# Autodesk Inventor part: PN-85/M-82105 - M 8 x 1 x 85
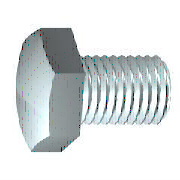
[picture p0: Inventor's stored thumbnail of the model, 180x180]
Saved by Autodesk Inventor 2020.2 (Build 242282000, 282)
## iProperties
Manager: www.cadconsulting.pl
Company: Fabian Stasiak CAD Consulting
Created: 2006-02
Part Number: PN-85/M-82105 - M 8 x 1 x 85
Material: Stal, miękka
Description: Wkręty z łbem sześciokątnym - A
Document SubType Name: Modeling
Standard: PN-85/M-82105
Designer: F.Stasiak
Standards Organization: PN
Language: pl-PL
Size Designation: M 8 x 1 x 85
Categories: <MemberInstance><Categories><Category DisplayName="Mocowania" InternalName="e4da775c-781d-43d5-af7c-5136215cf5a6" Mnemonic="FSTN"><Category DisplayName="Śruby"
Density: 7.86 g/cm^3
Mass: 39.4336 g
Surface Area: 26.4614 cm^2
Volume: 5.017 cm^3
Appearance: Metal-Stal
Author: F.Stasiak
Subject: Zbiór ćwiczeń. Autodesk Inventor 2020. Kurs podstawowy
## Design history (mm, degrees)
sketch "Szkic1"
  geometry: L1 (0, 5.8)-(0, 4); L2 (4, 4)-(85, 4); L3 (85, 4)-(85, 0); L4 (85, 0)-(-0.6, 0); L5 (-9.16, 0)-(110.68, 0) reference; L6 (-0.6, 0)-(-0.6, 5.8); L7 (-0.6, 5.8)-(0, 5.8); L8 (4, 4)-(3.386, 4); L9 (3.386, 4)-(0, 4); L10 (0, -0.58)-(0, 7.54) reference
  constraints: 16 end point, 2 collinear, 2 perpendicular, 1 parallel
  dimensions: "d0" = 85 distance between parallel lines of L3 L1 (= NLG); "d1" = 81 distance from line of L2.start L3 (= GEL); "d2" = 8 diameter of L2 L4 (= GD); "d9" = 0.6001 distance between parallel lines of L6 L1 (computed from SD); "d10" = 11.6 diameter of L7 L4 (= SD2); "d13" = 0.61355 distance of L2.start L8.end (computed from GAL); "d14" = 8 diameter of L9 L4 (= BDM)
revolve "Bryła" sketch "Szkic1" stored, may be unused: angle "d12" = 90 deg
sketch "Szkic2"
  geometry: L1 (0, 7.506)-(6.5, 3.753); L2 (6.5, 3.753)-(6.5, -3.753); L3 (6.5, -3.753)-(0, -7.506); L4 (0, -7.506)-(-6.5, -3.753); L5 (-6.5, -3.753)-(-6.5, 3.753); L6 (-6.5, 3.753)-(0, 7.506); 2 further points
  constraints: 12 end point, 1 coincident, 1 vertical, 11 other
  dimensions: "d11" = 13 distance between parallel lines of L5 L2 (= SW)
extrude "Głowica" join sketch "Szkic2" distance "d3" = 4.7 (= KOH - SD); taper "d4" = 0 deg
sketch "Szkic4"
  geometry: L1 (-5.3, 6.5)-(-5.3, 7.506); L2 (-5.3, 7.506)-(-4.72, 7.506); L3 (-4.72, 7.506)-(-5.3, 6.5); L4 (-5.77, 0)-(0.81, 0) reference; L5 (-0.6, 7.506)-(-5.3, 7.506) reference; L6 (-5.3, 3.753)-(-5.3, 7.506) reference
  constraints: 6 end point, 2 collinear, 1 perpendicular, 1 vertical
  dimensions: "d5" = 30 deg angle of L3 L1 (= ANG1); "d19" = 13 diameter of L1.start L4 (= SW0)
revolve "Faza1" sketch "Szkic4" stored, may be unused: angle "d21" = 90 deg
workplane "Work Plane1"
node "Bryła1"
node "Korpusy bryłowe"
node "Korpusy powierzchniowe"
feature "Gwint" dims "d15" = 81 (= GEL), "d16" = 0
chamfer "Faza2" distance "d6" = 0.61345 (= -0.5 x SPD + 0.5 x GD); stored, may be unused: second distance "d7" = 0.61355 (computed from GUL), angle "d55" = 45 deg
other parameters: "NLG" = 85 [user parameter; used in 1 equation term], "GD" = 8 (= NND) [user parameter; used in 2 equation terms], "BDM" = 8 (= NND) [user parameter; used in 1 equation term], "KOH" = 5.3 [user parameter; used in 1 equation term], "GEL" = 81 [user parameter; used in 2 equation terms], "SW" = 13 [user parameter; used in 3 equation terms], "SW0" = 13 (= SW) [user parameter; used in 1 equation term], "SPD" = 6.7731 (= NND - 1.2269 x PTC) [user parameter; used in 1 equation term], "SD2" = 11.6 (= SDH) [user parameter; used in 1 equation term], "SD" = 0.6 [user parameter; used in 3 equation terms], "ANG1" = 30 deg [user parameter; used in 1 equation term], "GAL" = 0.61345 (= 0.61345 x PTC) [user parameter; used in 2 equation terms], "GUL" = 0.61345 (= 0.61345 x PTC) [user parameter; used in 1 equation term], "d8" = 0, "RR" = 0.4 [user parameter], "d57" = 0, "d58" = 0, "WFT" = 0.6 (= SD) [user parameter], "GD1" = 6.7731 (= THREADDIA - 1.2269 x PTC) [user parameter], "THREADDIA" = 8 [user parameter; used in 1 equation term], "SDH" = 11.6 [user parameter; used in 1 equation term], "SDHG" = 0.61345 (= GAL) [user parameter], "TOA" = 30 deg [user parameter], "FAWI" = 45 deg [user parameter], "PTC" = 1 [user parameter; used in 5 equation terms], "NND" = 8 [user parameter; used in 3 equation terms], "E0" = 15.015 (= 1.155 x SW) [user parameter]
